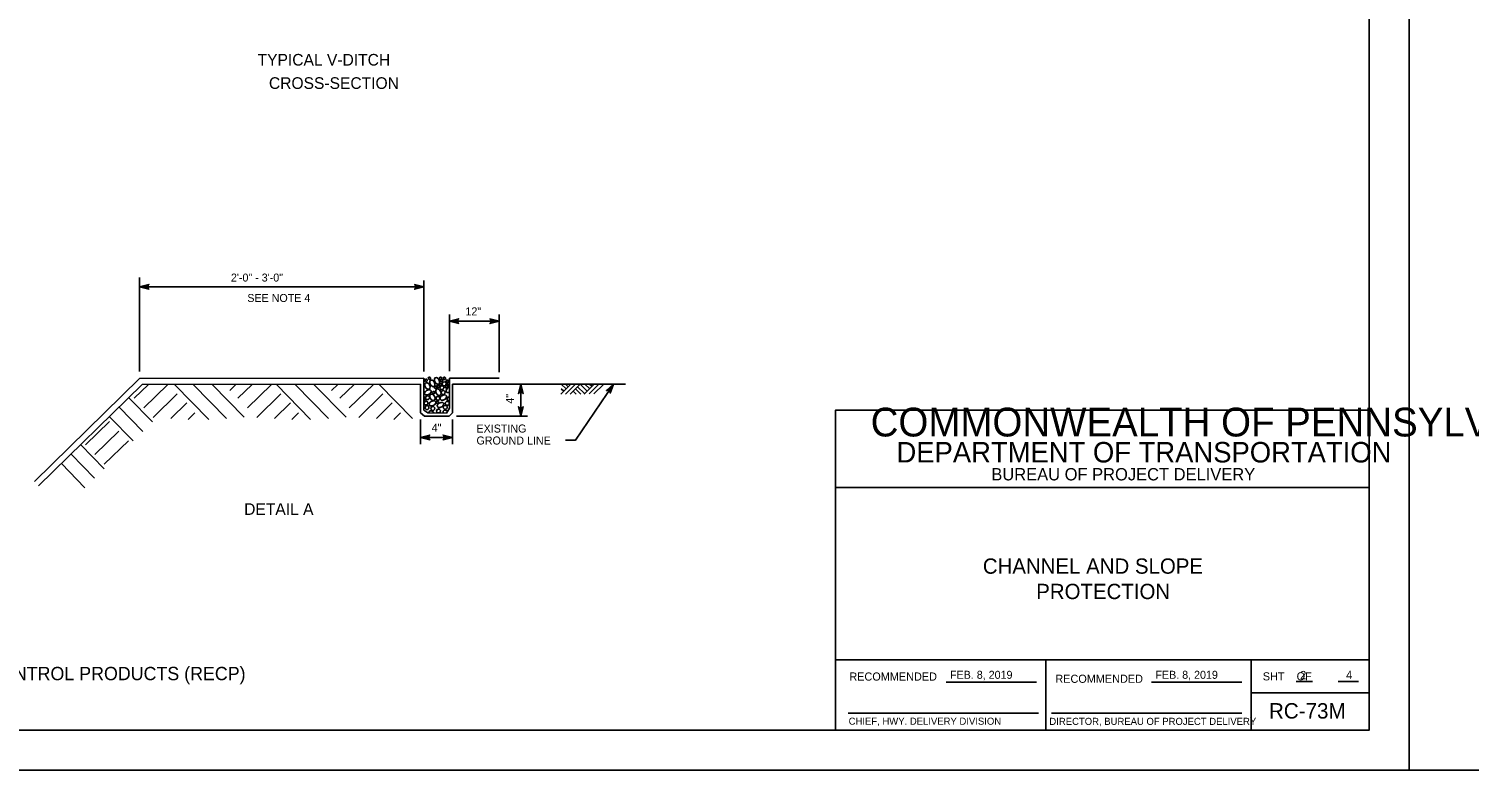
# Model space of a CAD drawing. Extents: x 636462 to 638208, y 299350 to 300538.
# Drawn here: x 636785 to 637325, y 299350 to 299628 of the extents above; entities that cross this region are included whole.
import ezdxf

# ---------------------------------------------------------------- set-up
doc = ezdxf.new("R2010")
doc.units = 0
for name, color, linetype in [('1', 7, 'Continuous'), ('Default', 7, 'Continuous'), ('PLT-BNDY', 7, 'Continuous')]:
    doc.layers.add(name, color=color, linetype=linetype)

msp = doc.modelspace()

# ---------------------------------------------------------------- linework, layer by layer
at = {"layer": '1'}
for p, q in [((637129.38, 299383.44), (637163.27, 299383.44)), ((637206.38, 299383.44), (637240.25, 299383.44)), ((637260.54, 299383.66), (637266.68, 299383.66)), ((637276.35, 299383.66), (637283.99, 299383.66)), ((637092.68, 299371.87), (637163.93, 299371.87)), ((637092.68, 299371.87), (637163.93, 299371.87)), ((637168.85, 299371.87), (637240.19, 299371.87)), ((637168.85, 299371.87), (637240.19, 299371.87))]:
    msp.add_line(p, q, dxfattribs=at)
msp.add_lwpolyline([(637287.91, 299365.45), (637287.91, 299929.45), (636501.91, 299929.45), (636501.91, 299365.45), (637287.91, 299365.45), (637287.91, 299391.81), (637087.91, 299391.81), (637087.91, 299456.49), (637287.91, 299456.49), (637287.91, 299485.45), (637087.91, 299485.45), (637087.91, 299365.45), (637166.72, 299365.45), (637166.72, 299391.81), (637166.72, 299365.45), (637243.72, 299365.45), (637243.72, 299391.81), (637243.72, 299379.49), (637287.91, 299379.49)], dxfattribs=at)
at = {"layer": 'Default'}
for p, q in [((636827, 299499.94), (636827, 299535.14)), ((636827, 299531.71), (636933.57, 299531.71)), ((636933.57, 299499.94), (636933.57, 299534.05)), ((636943.15, 299500.02), (636943.15, 299521.32)), ((636961.82, 299499.68), (636961.82, 299521.34)), ((636943.15, 299518.83), (636961.82, 299518.83)), ((636827, 299497.36), (636787.57, 299458.69)), ((636827.94, 299495.08), (636789.16, 299457.06)), ((636825.01, 299489.93), (636830.29, 299495.08)), ((636828.53, 299486.32), (636837.56, 299495.13)), ((636840.08, 299495.09), (636852.92, 299481.94)), ((636847.12, 299495.1), (636859.59, 299482.32)), ((636854.16, 299495.1), (636866.19, 299482.79)), ((636860.77, 299492.88), (636863.06, 299495.11)), ((636863.89, 299489.93), (636869.16, 299495.08)), ((636867.41, 299486.32), (636876.43, 299495.13)), ((636878.3, 299495.09), (636891.13, 299481.94)), ((636885.34, 299495.1), (636897.81, 299482.32)), ((636892.38, 299495.1), (636904.4, 299482.79)), ((636898.99, 299492.88), (636901.27, 299495.11)), ((636902.1, 299489.93), (636907.38, 299495.08)), ((636905.62, 299486.32), (636914.64, 299495.13)), ((636916.8, 299495.1), (636929.27, 299482.32)), ((636932.31, 299495.17), (636932.31, 299484.49)), ((636933.57, 299497.45), (636933.57, 299485.47)), ((636943.15, 299486.18), (636943.15, 299497.45)), ((636944.27, 299495.17), (636944.27, 299484.49)), ((636984.95, 299491.5), (636988.65, 299495.21)), ((636985.03, 299493.49), (636985.99, 299492.54)), ((636985.1, 299495.21), (636986.88, 299493.43)), ((636986.68, 299491.5), (636990.4, 299495.23)), ((636986.7, 299495.21), (636987.67, 299494.23)), ((636988.47, 299491.5), (636992.19, 299495.23)), ((636989.53, 299492.56), (636990.64, 299491.45)), ((636990.42, 299493.46), (636992.37, 299491.51)), ((636991.21, 299494.26), (636993.78, 299491.69)), ((636992.11, 299495.23), (636994.74, 299492.61)), ((636993.63, 299491.51), (636997.36, 299495.26)), ((636993.9, 299495.23), (636995.61, 299493.53)), ((636995.52, 299491.52), (636999.19, 299495.2)), ((636995.71, 299495.24), (636996.53, 299494.42)), ((636997.31, 299491.52), (637000.98, 299495.21)), ((636822.99, 299490.05), (636831.8, 299481.03)), ((636832.06, 299482.71), (636841.08, 299491.52)), ((636838.7, 299482.36), (636844.65, 299488.16)), ((636870.93, 299482.71), (636879.95, 299491.52)), ((636877.58, 299482.36), (636883.52, 299488.16)), ((636909.15, 299482.71), (636918.17, 299491.52)), ((636915.79, 299482.36), (636921.73, 299488.16)), ((636815.77, 299483), (636824.58, 299473.98)), ((636819.38, 299486.53), (636828.19, 299477.51)), ((636845.19, 299481.97), (636847.73, 299484.45)), ((636884.06, 299481.97), (636886.6, 299484.45)), ((636922.28, 299481.97), (636924.82, 299484.45)), ((636933.86, 299483.22), (636932.31, 299484.49)), ((636932.31, 299481.91), (636932.31, 299472.74)), ((636933.57, 299485.47), (636935.12, 299484.49)), ((636943, 299483.22), (636933.86, 299483.22)), ((636935.12, 299484.49), (636942.02, 299484.35)), ((636942.02, 299484.35), (636943.15, 299486.18)), ((636944.27, 299484.49), (636943, 299483.22)), ((636944.27, 299481.91), (636944.27, 299472.74)), ((636945.85, 299483.22), (636972.39, 299483.22)), ((636806.73, 299472.42), (636815.75, 299481.22)), ((636810.25, 299468.81), (636819.27, 299477.61)), ((636804.95, 299472.44), (636813.75, 299463.42)), ((636813.77, 299465.2), (636822.79, 299474)), ((636797.73, 299465.39), (636806.53, 299456.37)), ((636801.34, 299468.91), (636810.14, 299459.89))]:
    msp.add_line(p, q, dxfattribs=at)
for points in [[(636830.24, 299531.07), (636830.51, 299530.85), (636827, 299531.71), (636830.24, 299531.07), (636830.04, 299531.44), (636827, 299531.71), (636830.03, 299531.97), (636830.22, 299532.34), (636827, 299531.71), (636830.5, 299532.6), (636830.22, 299532.34)], [(636930.34, 299532.35), (636930.07, 299532.57), (636933.57, 299531.71), (636930.34, 299532.35), (636930.54, 299531.97), (636933.57, 299531.71), (636930.55, 299531.45), (636930.36, 299531.07), (636933.57, 299531.71), (636930.08, 299530.82), (636930.36, 299531.07)], [(636946.38, 299518.19), (636946.65, 299517.97), (636943.15, 299518.83), (636946.38, 299518.19), (636946.18, 299518.57), (636943.15, 299518.83), (636946.17, 299519.09), (636946.36, 299519.47), (636943.15, 299518.83), (636946.64, 299519.72), (636946.36, 299519.47)], [(636958.59, 299519.47), (636958.32, 299519.69), (636961.82, 299518.83), (636958.59, 299519.47), (636958.79, 299519.1), (636961.82, 299518.83), (636958.79, 299518.57), (636958.61, 299518.2), (636961.82, 299518.83), (636958.33, 299517.94), (636958.61, 299518.2)], [(636935.2, 299497.48), (636935.44, 299497.82), (636935.82, 299497.84), (636936.08, 299497.57), (636936.04, 299497.19), (636935.81, 299496.99), (636935.43, 299497.02), (636935.26, 299497.19), (636935.2, 299497.48)], [(636939.15, 299496.98), (636939.45, 299496.24), (636939.39, 299495.55), (636939.08, 299495.23), (636938.53, 299495.24), (636937.9, 299495.73), (636937.52, 299496.49), (636937.5, 299497.21), (636937.79, 299497.61), (636938.36, 299497.65), (636938.87, 299497.33), (636939.17, 299496.95)], [(636939.4, 299497.43), (636939.64, 299497.77), (636940.02, 299497.79), (636940.28, 299497.52), (636940.24, 299497.13), (636940.01, 299496.94), (636939.63, 299496.97), (636939.46, 299497.14), (636939.4, 299497.43)], [(636940.82, 299497.43), (636941.06, 299497.77), (636941.44, 299497.79), (636941.7, 299497.52), (636941.66, 299497.13), (636941.43, 299496.94), (636941.05, 299496.97), (636940.87, 299497.14), (636940.82, 299497.43)], [(636933.57, 299497.45), (636827, 299497.36)], [(636932.31, 299495.17), (636827.94, 299495.08)], [(636934.53, 299492.79), (636935.28, 299493.08), (636935.96, 299493.02), (636936.28, 299492.72), (636936.27, 299492.16), (636935.78, 299491.53), (636935.02, 299491.15), (636934.3, 299491.14), (636933.9, 299491.43), (636933.86, 299492), (636934.19, 299492.51), (636934.56, 299492.81)], [(636935.61, 299495.06), (636935.9, 299494.31), (636935.84, 299493.63), (636935.54, 299493.31), (636934.98, 299493.32), (636934.35, 299493.81), (636933.97, 299494.57), (636933.96, 299495.29), (636934.25, 299495.69), (636934.82, 299495.73), (636935.33, 299495.4), (636935.63, 299495.03)], [(636933.98, 299496.72), (636934.22, 299497.06), (636934.6, 299497.08), (636934.87, 299496.81), (636934.83, 299496.43), (636934.59, 299496.23), (636934.22, 299496.26), (636934.04, 299496.43), (636933.98, 299496.72)], [(636937.43, 299496.07), (636937.73, 299495.33), (636937.67, 299494.64), (636937.36, 299494.32), (636936.8, 299494.33), (636936.18, 299494.82), (636935.8, 299495.58), (636935.78, 299496.3), (636936.07, 299496.7), (636936.64, 299496.74), (636937.15, 299496.41), (636937.45, 299496.04)], [(636936.87, 299492.1), (636937.11, 299492.44), (636937.49, 299492.46), (636937.75, 299492.19), (636937.72, 299491.8), (636937.48, 299491.61), (636937.11, 299491.64), (636936.93, 299491.81), (636936.87, 299492.1)], [(636937.47, 299494.12), (636937.7, 299494.46), (636938.08, 299494.48), (636938.35, 299494.21), (636938.31, 299493.82), (636938.08, 299493.63), (636937.7, 299493.65), (636937.52, 299493.83), (636937.47, 299494.12)], [(636939.72, 299492.71), (636940.01, 299491.97), (636939.95, 299491.29), (636939.65, 299490.97), (636939.09, 299490.98), (636938.46, 299491.47), (636938.08, 299492.23), (636938.07, 299492.94), (636938.36, 299493.35), (636938.93, 299493.39), (636939.44, 299493.06), (636939.74, 299492.68)], [(636938.48, 299494.44), (636938.72, 299494.78), (636939.1, 299494.8), (636939.36, 299494.53), (636939.33, 299494.14), (636939.09, 299493.95), (636938.72, 299493.98), (636938.54, 299494.15), (636938.48, 299494.44)], [(636939.27, 299495.14), (636939.51, 299495.47), (636939.89, 299495.5), (636940.16, 299495.22), (636940.12, 299494.84), (636939.88, 299494.64), (636939.51, 299494.67), (636939.33, 299494.84), (636939.27, 299495.14)], [(636939.56, 299493.97), (636939.96, 299494.54), (636940.59, 299494.57), (636941.03, 299494.12), (636940.97, 299493.48), (636940.58, 299493.15), (636939.95, 299493.19), (636939.66, 299493.48), (636939.56, 299493.97)], [(636939.75, 299496.57), (636939.99, 299496.91), (636940.37, 299496.93), (636940.64, 299496.66), (636940.6, 299496.27), (636940.36, 299496.08), (636939.99, 299496.11), (636939.81, 299496.28), (636939.75, 299496.57)], [(636940.06, 299492.19), (636940.45, 299492.76), (636941.09, 299492.79), (636941.53, 299492.34), (636941.46, 299491.7), (636941.07, 299491.37), (636940.45, 299491.42), (636940.15, 299491.7), (636940.06, 299492.19)], [(636940.4, 299495.43), (636940.8, 299496), (636941.43, 299496.03), (636941.87, 299495.58), (636941.81, 299494.94), (636941.42, 299494.61), (636940.79, 299494.66), (636940.5, 299494.94), (636940.4, 299495.43)], [(636941.5, 299494.29), (636941.74, 299494.63), (636942.12, 299494.65), (636942.39, 299494.38), (636942.35, 299494), (636942.11, 299493.8), (636941.74, 299493.83), (636941.56, 299494), (636941.5, 299494.29)], [(636941.85, 299496.43), (636942.09, 299496.76), (636942.47, 299496.79), (636942.73, 299496.51), (636942.7, 299496.13), (636942.46, 299495.93), (636942.09, 299495.96), (636941.91, 299496.13), (636941.85, 299496.43)], [(636943.14, 299492.13), (636943.05, 299492.08), (636942.34, 299492.07), (636941.93, 299492.36), (636941.9, 299492.93), (636943.14, 299494.87)], [(636942.35, 299495.47), (636942.59, 299495.81), (636942.97, 299495.83), (636943.14, 299495.65)], [(636943.14, 299495.14), (636942.96, 299494.98), (636942.58, 299495.01), (636942.4, 299495.18), (636942.35, 299495.47)], [(636961.82, 299497.46), (636943.15, 299497.45)], [(637009.1, 299495.22), (636944.27, 299495.17)], [(636969.26, 299491.95), (636969.04, 299491.68), (636969.9, 299495.18), (636969.26, 299491.95), (636969.64, 299492.15), (636969.9, 299495.18), (636970.16, 299492.15), (636970.54, 299491.97), (636969.9, 299495.18), (636970.79, 299491.69), (636970.54, 299491.97)], [(636969.9, 299483.22), (636969.9, 299495.18)], [(636986.69, 299474.25), (636990.45, 299474.25), (637004.68, 299495.22)], [(637002.34, 299492.9), (637002, 299492.8), (637004.68, 299495.22), (637002.34, 299492.9), (637002.76, 299492.85), (637004.68, 299495.22), (637003.19, 299492.57), (637003.4, 299492.2), (637004.68, 299495.22), (637003.45, 299491.83), (637003.4, 299492.2)], [(636933.57, 299490.42), (636933.65, 299490.42), (636934.09, 299489.97), (636934.03, 299489.33), (636933.64, 299489), (636933.57, 299489)], [(636933.63, 299488.23), (636934.03, 299488.8), (636934.66, 299488.83), (636935.1, 299488.37), (636935.04, 299487.73), (636934.65, 299487.41), (636934.02, 299487.45), (636933.73, 299487.74), (636933.63, 299488.23)], [(636934, 299486.54), (636934.4, 299487.1), (636935.03, 299487.14), (636935.48, 299486.68), (636935.41, 299486.04), (636935.02, 299485.72), (636934.39, 299485.76), (636934.1, 299486.05), (636934, 299486.54)], [(636934.16, 299490.24), (636934.56, 299490.8), (636935.19, 299490.84), (636935.63, 299490.38), (636935.57, 299489.74), (636935.18, 299489.41), (636934.55, 299489.46), (636934.26, 299489.75), (636934.16, 299490.24)], [(636936.29, 299488.68), (636937.04, 299488.98), (636937.72, 299488.92), (636938.04, 299488.61), (636938.03, 299488.06), (636937.54, 299487.43), (636936.78, 299487.05), (636936.06, 299487.03), (636935.66, 299487.32), (636935.62, 299487.89), (636935.95, 299488.4), (636936.32, 299488.7)], [(636937.47, 299490.84), (636937.77, 299490.1), (636937.71, 299489.42), (636937.4, 299489.09), (636936.85, 299489.1), (636936.22, 299489.59), (636935.84, 299490.35), (636935.82, 299491.07), (636936.11, 299491.48), (636936.68, 299491.51), (636937.19, 299491.19), (636937.49, 299490.81)], [(636936.17, 299486.19), (636936.57, 299486.76), (636937.21, 299486.79), (636937.65, 299486.34), (636937.58, 299485.7), (636937.19, 299485.37), (636936.57, 299485.42), (636936.27, 299485.7), (636936.18, 299486.19)], [(636938.04, 299490.01), (636938.44, 299490.57), (636939.07, 299490.61), (636939.52, 299490.15), (636939.45, 299489.51), (636939.06, 299489.19), (636938.43, 299489.23), (636938.14, 299489.52), (636938.04, 299490.01)], [(636938.23, 299488.51), (636938.46, 299488.85), (636938.84, 299488.87), (636939.11, 299488.59), (636939.07, 299488.21), (636938.83, 299488.01), (636938.46, 299488.04), (636938.28, 299488.21), (636938.23, 299488.51)], [(636939.25, 299488.07), (636940, 299488.37), (636940.68, 299488.31), (636941, 299488), (636940.99, 299487.45), (636940.5, 299486.82), (636939.74, 299486.44), (636939.02, 299486.42), (636938.62, 299486.71), (636938.58, 299487.28), (636938.91, 299487.79), (636939.28, 299488.09)], [(636940.33, 299490.88), (636941.08, 299491.17), (636941.76, 299491.11), (636942.08, 299490.81), (636942.07, 299490.25), (636941.58, 299489.62), (636940.82, 299489.24), (636940.1, 299489.23), (636939.7, 299489.52), (636939.66, 299490.09), (636939.99, 299490.6), (636940.36, 299490.9)], [(636940.86, 299486.65), (636941.26, 299487.22), (636941.89, 299487.25), (636942.33, 299486.79), (636942.27, 299486.15), (636941.88, 299485.83), (636941.25, 299485.87), (636940.95, 299486.16), (636940.86, 299486.65)], [(636941.61, 299488.14), (636942, 299488.71), (636942.64, 299488.75), (636943.08, 299488.29), (636943.01, 299487.65), (636942.62, 299487.32), (636942, 299487.37), (636941.7, 299487.65), (636941.61, 299488.14)], [(636942.26, 299489.8), (636942.65, 299490.36), (636943.14, 299490.39)], [(636943.14, 299488.99), (636942.65, 299489.02), (636942.35, 299489.31), (636942.26, 299489.8)], [(636935.54, 299484.54), (636935.54, 299484.8), (636935.82, 299485.2), (636936.39, 299485.24), (636936.9, 299484.92), (636937.2, 299484.54)], [(636938.31, 299485.23), (636938.71, 299485.8), (636939.34, 299485.83), (636939.78, 299485.38), (636939.72, 299484.74), (636939.33, 299484.41), (636938.7, 299484.46), (636938.41, 299484.74), (636938.31, 299485.23)], [(636940.84, 299484.36), (636940.83, 299485.07), (636941.12, 299485.47), (636941.69, 299485.51), (636942.2, 299485.18), (636942.37, 299484.97)], [(636970.54, 299486.45), (636970.76, 299486.72), (636969.9, 299483.22), (636970.54, 299486.45), (636970.17, 299486.26), (636969.9, 299483.22), (636969.64, 299486.25), (636969.27, 299486.43), (636969.9, 299483.22), (636969.01, 299486.71), (636969.27, 299486.43)], [(636935.54, 299474.59), (636935.81, 299474.37), (636932.31, 299475.23), (636935.54, 299474.59), (636935.34, 299474.97), (636932.31, 299475.23), (636935.34, 299475.49), (636935.52, 299475.87), (636932.31, 299475.23), (636935.8, 299476.12), (636935.52, 299475.87)], [(636941.04, 299475.87), (636940.77, 299476.09), (636944.27, 299475.23), (636941.04, 299475.87), (636941.24, 299475.5), (636944.27, 299475.23), (636941.24, 299474.97), (636941.06, 299474.6), (636944.27, 299475.23), (636940.78, 299474.34), (636941.06, 299474.6)], [(636932.31, 299475.23), (636944.27, 299475.23)]]:
    msp.add_lwpolyline(points, dxfattribs=at)
at = {"layer": 'PLT-BNDY'}
for points in [[(636461.91, 299944.45), (637302.91, 299944.45), (637302.91, 299350.45), (636461.91, 299350.45)], [(637302.91, 299944.45), (638143.91, 299944.45), (638143.91, 299350.45), (637302.91, 299350.45)]]:
    msp.add_lwpolyline(points, close=True, dxfattribs=at)

# ---------------------------------------------------------------- texts
at = {"layer": '1'}
for s, height, p in [('COMMONWEALTH OF PENNSYLVANIA', 10.7834, (637101.07, 299475.59)), ('DEPARTMENT OF TRANSPORTATION', 7.6843, (637110.75, 299465.84)), ('BUREAU OF PROJECT DELIVERY', 4.6221, (637146.32, 299459.11)), ('RECOMMENDED', 3.048, (637093.08, 299384.04)), ('FEB. 8, 2019', 3, (637130.82, 299384.72)), ('RECOMMENDED', 3.048, (637170.32, 299383.21)), ('FEB. 8, 2019', 3, (637207.82, 299384.72)), ('SHT    OF', 3.048, (637248.08, 299384.12)), ('2', 3.13, (637262.05, 299384.54)), ('4', 3.13, (637279.28, 299384.59)), ('APPROVED', 0.0192, (637130.94, 299383.38)), ('APPROVED', 0.0192, (637130.94, 299383.38)), ('APPROVED', 0.0192, (637130.94, 299383.38)), ('APPROVED', 0.0192, (637130.94, 299383.38)), ('CHIEF, HWY. DELIVERY DIVISION', 2.6623, (637092.82, 299367.49)), ('CHIEF, HWY. DELIVERY DIVISION', 2.6623, (637092.82, 299367.49)), ('DIRECTOR, BUREAU OF PROJECT DELIVERY', 2.6623, (637168.07, 299367.43)), ('DIRECTOR, BUREAU OF PROJECT DELIVERY', 2.6623, (637168.07, 299367.43))]:
    msp.add_text(s, height=height, dxfattribs=at).set_placement(p)
at = {"layer": 'Default'}
for s, height, p in [('TYPICAL V-DITCH', 4.3721, (636871.24, 299614.65)), ('CROSS-SECTION', 4.3721, (636875.49, 299605.91)), ('2\'-0" - 3\'-0"', 2.998, (636861.24, 299533.67)), ('SEE NOTE 4', 2.998, (636867.39, 299526.02)), ('12"', 2.998, (636949.16, 299520.99)), ('4"', 2.998, (636936.5, 299477.34)), ('EXISTING', 2.998, (636953.3, 299477.06)), ('GROUND LINE', 2.998, (636953.3, 299472.57)), ('DETAIL A', 4.372, (636866.2, 299446.17)), ('CHANNEL AND SLOPE', 5.7257, (637143.13, 299424.12)), ('PROTECTION', 5.726, (637163.14, 299414.61)), ('ROLLED EROSION CONTROL PRODUCTS (RECP)', 4.9967, (636708.57, 299384.2)), ('RC-73M', 5.779, (637250.37, 299369.81))]:
    msp.add_text(s, height=height, dxfattribs=at).set_placement(p)
msp.add_text('4"', height=2.998, rotation=90, dxfattribs=at).set_placement((636967.3, 299487.88))

doc.saveas('drawing.dxf')
